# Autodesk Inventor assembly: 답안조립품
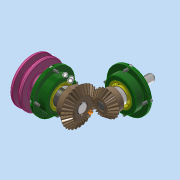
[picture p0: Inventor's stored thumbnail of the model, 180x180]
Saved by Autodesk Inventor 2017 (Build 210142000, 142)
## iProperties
Part Number: 답안조립품
Material: 일반
Document SubType Name: Assembly
Designer: MRC
Author: MRC
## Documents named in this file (17)
- C:\Users\MRC\Desktop\730108V1002\답안조립품.iam
- C:\Users\MRC\Desktop\730108V1002\V-벨트풀리.ipt
- C:\Users\MRC\Desktop\730108V1002\메인 베벨기어.ipt
- C:\Users\MRC\Desktop\730108V1002\메인 축.ipt
- 메인 축.ipt
- C:\Users\MRC\Desktop\730108V1002\베어링 6203.ipt
- C:\Users\MRC\Desktop\730108V1002\본체.ipt
- C:\Users\MRC\Desktop\730108V1002\볼트 M4 x 10.ipt
- C:\Users\MRC\Desktop\730108V1002\서브 베벨기어.ipt
- C:\Users\MRC\Desktop\730108V1002\서브 축.ipt
- 서브 축.ipt
- C:\Users\MRC\Desktop\730108V1002\오일실 17 x 32 x 8.ipt
- C:\Users\MRC\Desktop\730108V1002\와셔 4 x 16.ipt
- C:\Users\MRC\Desktop\730108V1002\육각볼트 M4 x 8.ipt
- C:\Users\MRC\Desktop\730108V1002\커버.ipt
- C:\Users\MRC\Desktop\730108V1002\키 4 x 4 x 14.ipt
- C:\Users\MRC\Desktop\730108V1002\키 5 x 5 x 14.ipt
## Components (1 placed, 1 different names)
1. V-벨트풀리:1
